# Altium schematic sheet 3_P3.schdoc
size 431 x 309 mm; Symbol: Sheet-Symbol_A4; Device: Sheet-Symbol_A4; @Page Name: P3; @Create Date: 2022-12-06; @Page Count: 3; @Page No: 3; @Project Name: MainBoard; @Schematic Name: Schematic1; @Update Date: 2022-12-29 15:32:21; Company: 嘉立创EDA; Page Size: A4; Version: V1.0
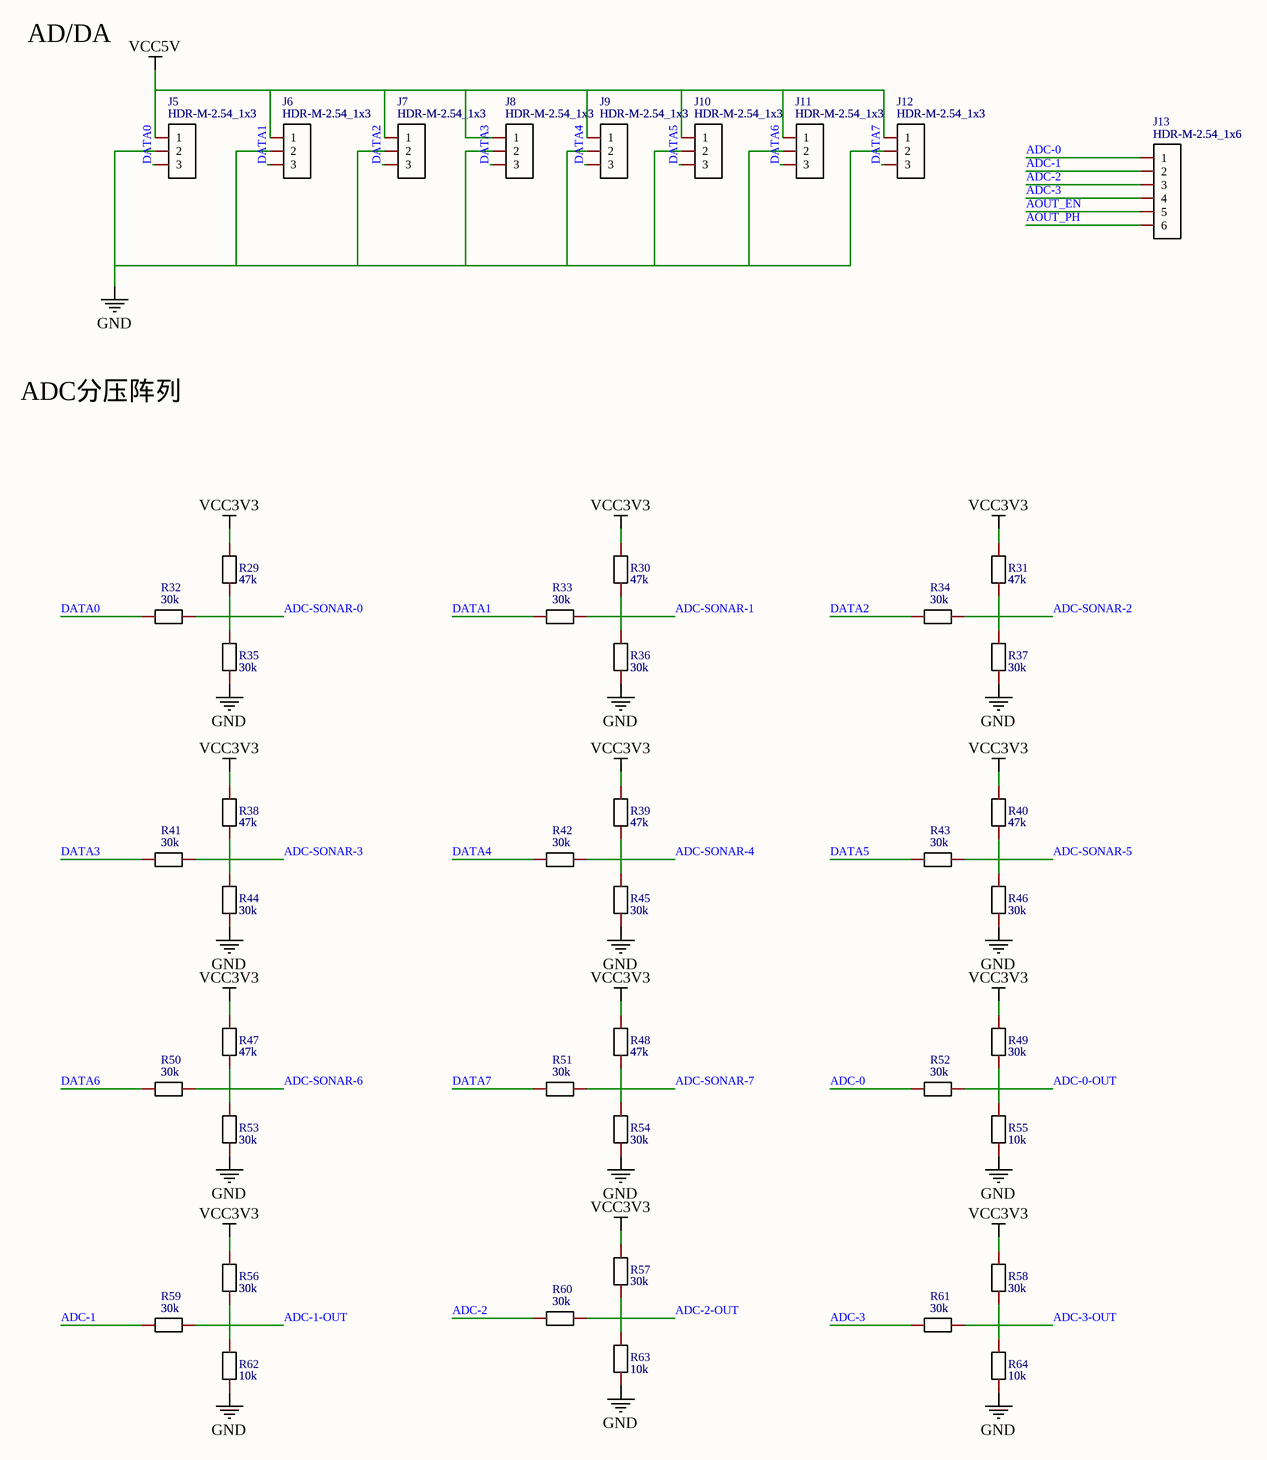
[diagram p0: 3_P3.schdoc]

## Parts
J5  HDR-M-2.54_1x3  [HDR-M-2.54_1X3]
J6  HDR-M-2.54_1x3  [HDR-M-2.54_1X3]
J7  HDR-M-2.54_1x3  [HDR-M-2.54_1X3]
J8  HDR-M-2.54_1x3  [HDR-M-2.54_1X3]
J9  HDR-M-2.54_1x3  [HDR-M-2.54_1X3]
J10  HDR-M-2.54_1x3  [HDR-M-2.54_1X3]
J11  HDR-M-2.54_1x3  [HDR-M-2.54_1X3]
J12  HDR-M-2.54_1x3  [HDR-M-2.54_1X3]
J13  HDR-M-2.54_1x6  [HDR-M-2.54_1X6]
R29  47k  [R0603]
R30  47k  [R0603]
R31  47k  [R0603]
R32  30k  [R0603]
R33  30k  [R0603]
R34  30k  [R0603]
R35  30k  [R0603]
R36  30k  [R0603]
R37  30k  [R0603]
R38  47k  [R0603]
R39  47k  [R0603]
R40  47k  [R0603]
R41  30k  [R0603]
R42  30k  [R0603]
R43  30k  [R0603]
R44  30k  [R0603]
R45  30k  [R0603]
R46  30k  [R0603]
R47  47k  [R0603]
R48  47k  [R0603]
R49  30k  [R0603]
R50  30k  [R0603]
R51  30k  [R0603]
R52  30k  [R0603]
R53  30k  [R0603]
R54  30k  [R0603]
R55  10k  [R0603]
R56  30k  [R0603]
R57  30k  [R0603]
R58  30k  [R0603]
R59  30k  [R0603]
R60  30k  [R0603]
R61  30k  [R0603]
R62  10k  [R0603]
R63  10k  [R0603]
R64  10k  [R0603]

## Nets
GND: J5.2 J6.2 J7.2 J8.2 J9.2 J10.2 J11.2 J12.2 R35.1 R36.1 R37.1 R44.1 R45.1 R46.1 R53.1 R54.1 R55.1 R62.1 R63.1 R64.1
VCC3V3: R29.2 R30.2 R31.2 R38.2 R39.2 R40.2 R47.2 R48.2 R49.2 R56.2 R57.2 R58.2
VCC5V: J5.1 J6.1 J7.1 J8.1 J9.1 J10.1 J11.1 J12.1
ADC-0: J13.1 R52.1
ADC-0-OUT: R49.1 R52.2 R55.2
ADC-1: J13.2 R59.1
ADC-1-OUT: R56.1 R59.2 R62.2
ADC-2: J13.3 R60.1
ADC-2-OUT: R57.1 R60.2 R63.2
ADC-3: J13.4 R61.1
ADC-3-OUT: R58.1 R61.2 R64.2
ADC-SONAR-0: R29.1 R32.2 R35.2
ADC-SONAR-1: R30.1 R33.2 R36.2
ADC-SONAR-2: R31.1 R34.2 R37.2
ADC-SONAR-3: R38.1 R41.2 R44.2
ADC-SONAR-4: R39.1 R42.2 R45.2
ADC-SONAR-5: R40.1 R43.2 R46.2
ADC-SONAR-6: R47.1 R50.2 R53.2
ADC-SONAR-7: R48.1 R51.2 R54.2
AOUT_EN: J13.5
AOUT_PH: J13.6
DATA0: J5.3 R32.1
DATA1: J6.3 R33.1
DATA2: J7.3 R34.1
DATA3: J8.3 R41.1
DATA4: J9.3 R42.1
DATA5: J10.3 R43.1
DATA6: J11.3 R50.1
DATA7: J12.3 R51.1

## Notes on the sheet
- AD/DA
- ADC分压阵列

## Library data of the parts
J5-J12 = HDR-M-2.54_1x3: Convert to PCB: yes
J13 = HDR-M-2.54_1x6: Convert to PCB: yes
R29-R31 R38-R40 R47-R49 R56-R58 = 11k: Convert to PCB: yes
R32-R34 R41-R43 R50 R51 = 1k: Convert to PCB: yes
R35-R37 R44-R46 R53 R54 = 1.65k: Convert to PCB: yes
R52 R59-R61 = 3.4k: Convert to PCB: yes
R55 R63 = 1.4k: Convert to PCB: yes
R62 R64 = 1.4k: Convert to PCB: yes; NUMBER: 2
